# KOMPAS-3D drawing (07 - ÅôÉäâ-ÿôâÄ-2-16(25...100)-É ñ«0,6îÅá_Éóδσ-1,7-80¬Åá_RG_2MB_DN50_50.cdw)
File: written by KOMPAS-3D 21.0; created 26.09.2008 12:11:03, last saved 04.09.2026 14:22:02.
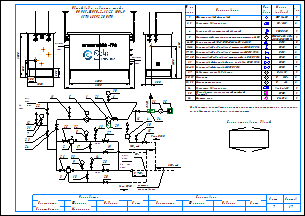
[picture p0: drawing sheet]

Sheets 1-2: A3, landscape

Document properties: Наименование: Макро:21; Автор: RaskoAdmin; Форматы листов документа: 2xA3; Полное имя файла: \\ur38nt01\Departments\КТО\КБ ПУРДГ\Заявки\Прайс-лист на типовые шкафы ГРПШ\ПУРДГ_стандарт_30_04_2026\ПУРДГ с RG_2MB\ПУРДГ-ШУГО-2-16(25...100)-Р до0,6МПа_Рвых-1,7-80кПа_RG_2MB_DN50_50.cdw

Title block, sheet 1: Наименование: Пункт учета газа / ПУГ-Ш-400-Р / ЛГТИ.485922.001ТУ; designation: ЛГТИ.03.4411141; sheet number: 1; Количество листов документа: 2; organisation: ООО "ЭЛЬСТЕР Газэлектроника"; Форматы листов документа: A3; stored path: C:\Рабочие документы\Компас\ПУГ\Схема.cdw; Разработал: Устинов; Проверил: Кошкин; Утвердил: Кошкин
Title block, sheet 2: sheet number: 2; stored path: D:\Рабочие документы\Заявки\ПУРДГ\ПУРДГ-ШУЭО-2-100-Р 4411220.cdw; designation, second copy: ЛГТИ.03.4411141-

Views: Вид 1, Вид 2
Referenced files: wcvoit.frw
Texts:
  Normal
  № на
  схеме
  Усл.
  обозн.
  Марка
  (модель)
  Кол.
  Фильтр газовый фланцевый
  ФГ 16-50
  Регулятор давления газа
  RG/2MB
  Клапан предохранительный сбросной
  КПС DN20
  Измерительный комплекс с ротационным счетчиком Ду50
  СГ-ЭК-Р-(0,2...2,0)-
  Кран кнопочный VE-РАСКО-НЗ-1,6-G1/2-М20
  DN15
  Кран шаровой "под приварку" штуцерный DN20 PN16
  DN20
  Кран шаровой "под приварку" штуцерный DN15 PN16
  Кран шаровой "под приварку" штуцерный п/п DN20 PN16
  Кран шаровой фланцевый с мех. приводом DN50 PN16
  Кран шаровой фланцевый DN50 PN16
  DN50
  Индикатор перепада давления
  Манометр
  Манометр-напоромер
  Обогреватель газогорелочный шкафной
  (Эльтон")
  Счетчик газа
  Delta 15
  0...     МПа
  0...     кПа
  Venio-A-15
  ОГШН
  BK-G1,6
  Общий вид и габариты шкафа
  ПУРДГ-ШУГО-2-16(25...100)-Р
  Выход газа
  Вход газа
  logo-rasko-ge.png
  DN 1
  местное
  сопротивление
  Римп DN20
  Выход
  газа
  Р=     кПа
  Вход
  Р=       МПа
  PDI
  Схема открывания дверей
  Предприятие изготовитель может заменять комплектующие на аналогичные,
  не ухудшающие заявленных характеристик.
  Должность
  Конструктор
  Фамилия
  Подпись
  Дата
  Согласовано
  Максимкин
  Лист
  Листов
  POLYLINE_STYLE_0.18_RGB_0_0_0
  POLYLINE_STYLE_0.50_RGB_0_0_0
  POLYLINE_STYLE_0.34_RGB_0_0_0
  PHANTOM_RGB_0_0_0_SC_1_THICK_0.18
  K5LT_THIN_RGB_0_0_0_THICK_0.18
  K5LT32769_RGB_0_0_0_THICK_0.18
  K5LT12_RGB_0_0_0_SC_1_THICK_0.18
  K5LT_DASHED_RGB_0_0_0_SC_1_THICK_0.18
  ACISOTGL_RGB_0_0_0_SC_0.8_THICK_0.25
  CONTINUOUS_RGB_0_127_31_THICK_0.3
  CONTINUOUS_RGB_0_0_255_THICK_0.35
  CONTINUOUS_RGB_255_0_0_THICK_0.35
  POLYLINE_STYLE_0.25_RGB_0_0_0
  CONTINUOUS_RGB_0_0_0_THICK_0.5
  POLYLINE_STYLE_0.35_RGB_0_0_255
  CONTINUOUS_RGB_0_0_0_THICK_0.4
  CONTINUOUS_RGB_0_0_0_THICK_0.35
  НЕВИДИМАЯ_RGB_0_0_0_SC_0.3_THICK_0.25
  СONTINUOUS_RGB_0_0_0_THICK_0.25
  ОСЕВАЯ2_RGB_248_153_30_SC_0.3_THICK_0.25
  Без оформления
Dimensions and other numbers on the sheet: 1; 2, 3; 2; 4; 5; 6-10; 11-16; 6; 17, 18; 19, 20; 21; 22-28; 7; 29; 30, 31; 32, 33; 34; 35; 36; 1500; 250; 300; 1050; 550; 305; 2000; 4130; 2300; 5,,,7DN 1; 31; 12; 22; 23; 24; 11; 30; 25; 32; 8; 17; 13; 27; 19; 10; 15; 26; 33; 9; 3; 18; 14; 28; 20; 16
